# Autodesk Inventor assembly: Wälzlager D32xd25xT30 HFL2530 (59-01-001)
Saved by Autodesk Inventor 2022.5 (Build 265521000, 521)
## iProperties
Created: 2024-12
Part Number: Wälzlager D32xd25xT30 HFL2530 (59-01-001)
Document SubType Name: Assembly
Designer: AdminForWorker
Title: Wälzlager D32xd25xT30 HFL2530 (59-01-001) v1
Author: AdminForWorker
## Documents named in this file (6)
- c:\worker\convert-fusion-r05-cosv3\tmp\job-1\61\temp\files\e2bc116e-41de-4bbb-9873-548417da8672\9e750b68-f6a3-40eb-86cf-f551caf2fd2a.zip.iam
- c:\worker\convert-fusion-r05-cosv3\tmp\job-1\61\temp\files\e2bc116e-41de-4bbb-9873-548417da8672\HFL2530_OuterRing.ipt
- c:\worker\convert-fusion-r05-cosv3\tmp\job-1\61\temp\files\e2bc116e-41de-4bbb-9873-548417da8672\HFL2530_Cage1.ipt
- c:\worker\convert-fusion-r05-cosv3\tmp\job-1\61\temp\files\e2bc116e-41de-4bbb-9873-548417da8672\HFL2530_Cage2.ipt
- c:\worker\convert-fusion-r05-cosv3\tmp\job-1\61\temp\files\e2bc116e-41de-4bbb-9873-548417da8672\HFL2530_Roller1.ipt
- c:\worker\convert-fusion-r05-cosv3\tmp\job-1\61\temp\files\e2bc116e-41de-4bbb-9873-548417da8672\HFL2530_Roller2.ipt
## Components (70 placed, 5 different names)
1. HFL2530_OuterRing:1
2. HFL2530_Cage1:1
3. HFL2530_Cage2:1
4. HFL2530_Cage2:2
5. HFL2530_Roller1:1
6. HFL2530_Roller1:2
7. HFL2530_Roller1:3
8. HFL2530_Roller1:4
9. HFL2530_Roller1:5
10. HFL2530_Roller1:6
11. HFL2530_Roller1:7
12. HFL2530_Roller1:8
13. HFL2530_Roller1:9
14. HFL2530_Roller1:10
15. HFL2530_Roller1:11
16. HFL2530_Roller1:12
17. HFL2530_Roller1:13
18. HFL2530_Roller1:14
19. HFL2530_Roller1:15
20. HFL2530_Roller1:16
21. HFL2530_Roller1:17
22. HFL2530_Roller1:18
23. HFL2530_Roller1:19
24. HFL2530_Roller1:20
25. HFL2530_Roller1:21
26. HFL2530_Roller1:22
27. HFL2530_Roller2:1
28. HFL2530_Roller2:2
29. HFL2530_Roller2:3
30. HFL2530_Roller2:4
31. HFL2530_Roller2:5
32. HFL2530_Roller2:6
33. HFL2530_Roller2:7
34. HFL2530_Roller2:8
35. HFL2530_Roller2:9
36. HFL2530_Roller2:10
37. HFL2530_Roller2:11
38. HFL2530_Roller2:12
39. HFL2530_Roller2:13
40. HFL2530_Roller2:14
41. HFL2530_Roller2:15
42. HFL2530_Roller2:16
43. HFL2530_Roller2:17
44. HFL2530_Roller2:18
45. HFL2530_Roller2:19
46. HFL2530_Roller2:20
47. HFL2530_Roller2:21
48. HFL2530_Roller2:22
49. HFL2530_Roller2:23
50. HFL2530_Roller2:24
51. HFL2530_Roller2:25
52. HFL2530_Roller2:26
53. HFL2530_Roller2:27
54. HFL2530_Roller2:28
55. HFL2530_Roller2:29
56. HFL2530_Roller2:30
57. HFL2530_Roller2:31
58. HFL2530_Roller2:32
59. HFL2530_Roller2:33
60. HFL2530_Roller2:34
61. HFL2530_Roller2:35
62. HFL2530_Roller2:36
63. HFL2530_Roller2:37
64. HFL2530_Roller2:38
65. HFL2530_Roller2:39
66. HFL2530_Roller2:40
67. HFL2530_Roller2:41
68. HFL2530_Roller2:42
69. HFL2530_Roller2:43
70. HFL2530_Roller2:44
